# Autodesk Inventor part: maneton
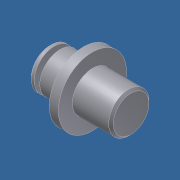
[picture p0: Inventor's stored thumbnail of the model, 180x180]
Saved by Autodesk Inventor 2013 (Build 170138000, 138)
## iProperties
Created: 2011-07
Part Number: maneton
Document SubType Name: Modeling
Designer: Laur
Density: 7.85 g/cm^3
Material: Acier allié
Mass: 0.637262 g
Surface Area: 1.50499 cm^2
Volume: 0.0811799 cm^3
Author: Laur
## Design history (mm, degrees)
sketch "Esquisse1"
  geometry: L1 (0, 0)-(7.2, 0); L2 (0, 0)-(0, 1.57); L3 (0, 1.57)-(0.2, 1.77); L4 (0.2, 1.77)-(0.44, 1.77); L5 (0.44, 1.77)-(0.44, 1); L6 (0.44, 1)-(0.94, 1); L7 (0.94, 1)-(0.94, 1.77); L8 (0.94, 1.77)-(3, 1.77); L9 (3, 1.77)-(3, 3); L10 (3, 3)-(3.8, 3); L11 (3.8, 3)-(3.8, 1.77); L12 (3.8, 1.77)-(7.2, 1.77); L13 (7.2, 1.77)-(7.2, 0)
  constraints: 27 end point, 6 parallel, 3 perpendicular, 2 collinear, 1 horizontal
  dimensions: "d0" = 0.5 distance between parallel lines of L7 L5; "d1" = 3.54 diameter of L4 L1; "d2" = 3.54 diameter of L8 L1 (= d1); "d3" = 3.54 diameter of L12 L1 (= d1); "d4" = 6 diameter of L10 L1; "d5" = 0.8 distance between parallel lines of L11 L9; "d6" = 7.2 distance between parallel lines of L13 L2; "d7" = 2 diameter of L6 L1; "d8" = 0.44 distance between parallel lines of L5 L2; "d9" = 45 deg angle of L2 L3; "d10" = 0.2 distance from line of L2 L3.end; "d11" = 3 distance between parallel lines of L9 L2
revolve "arbre dont Ø3,54" sketch "Esquisse1" stored, may be unused: angle "d12" = 90 deg
chamfer "Chanfrein 0,2 à 45°" distance "d13" = 0.2; stored, may be unused: second distance "d14" = 2, angle "d15" = 45 deg
node "Solide1"
node "Corps solides"
node "Corps surfaciques"
